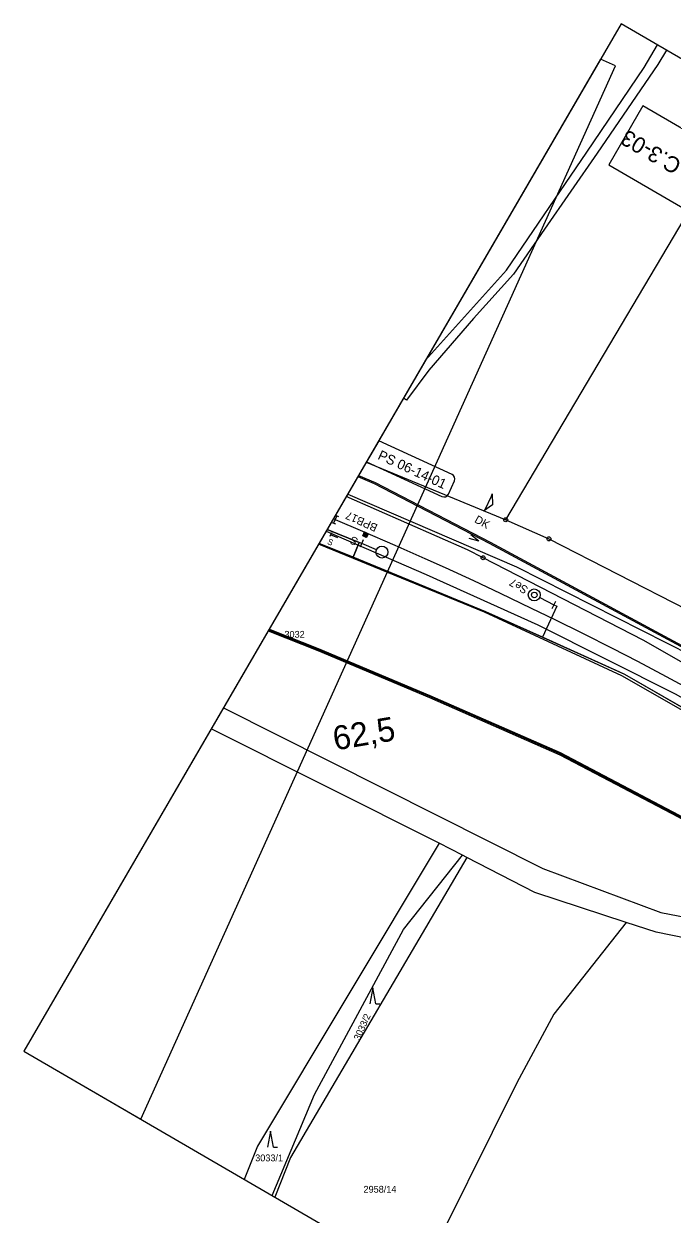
# Model space of a CAD drawing. Extents: x -621168 to -620292, y -1122748 to -1122069.
# Drawn here: x -621167.8 to -621005.8, y -1122366.6 to -1122069.2 of the extents above; entities that cross this region are included whole.
import ezdxf

# ---------------------------------------------------------------- set-up
doc = ezdxf.new("R2010")
doc.units = 0
for name, color, linetype in [('CETIN', 7, 'Continuous'), ('hm', 7, 'Continuous'), ('HranDP', 7, 'Continuous'), ('Hranice parcel', 7, 'Continuous'), ('itself', 7, 'Continuous'), ('lomové body trasa', 7, 'Continuous'), ('Parcelní čísla', 7, 'Continuous'), ('PS 06-14-01_trasa_sdělovací_nové', 7, 'Continuous'), ('PS6-14-01_bubliny', 7, 'Continuous'), ('Razítka', 7, 'Continuous'), ('Rámečky-tisk', 7, 'Continuous'), ('SSZT', 7, 'Continuous'), ('SSZT-DK', 7, 'Continuous'), ('STANICENI NOVE HM', 7, 'Continuous'), ('Vrstva 1', 7, 'Continuous'), ('Vrstva 2', 7, 'Continuous'), ('Vrstva 3', 7, 'Continuous'), ('Vrstva 6', 7, 'Continuous'), ('Věcná břemena k části', 7, 'Continuous'), ('Značky bodu BP', 7, 'Continuous'), ('Značky kultur', 7, 'Continuous'), ('ČD-T', 7, 'Continuous')]:
    doc.layers.add(name, color=color, linetype=linetype)

msp = doc.modelspace()

# ---------------------------------------------------------------- linework, layer by layer
at = {"layer": 'CETIN'}
msp.add_lwpolyline([(-621086.89, -1122186.72), (-621044.7, -1122204.84), (-620975.94, -1122239.69), (-620943.1, -1122258.62), (-620748.44, -1122376.27), (-620484.52, -1122538.15)], dxfattribs=at)
at = {"layer": 'hm'}
msp.add_line((-621052.05, -1122209.91), (-621052.05, -1122209.91), dxfattribs=at)
at = {"layer": 'HranDP'}
for points in [[(-620988.93, -1122236.95), (-621013.01, -1122223.23), (-621053.04, -1122202.61), (-621056.92, -1122200.6), (-621087.23, -1122187.32)], [(-620902.62, -1122306.44), (-620922.25, -1122290.14), (-620980.18, -1122253.91), (-621018.36, -1122232.1), (-621052.69, -1122216.23), (-621094.17, -1122199.24)]]:
    msp.add_lwpolyline(points, dxfattribs=at)
at = {"layer": 'Hranice parcel'}
for p, q in [((-621058.23, -1122276.92), (-621064.04, -1122273.91)), ((-621057.09, -1122277.51), (-621058.23, -1122276.92))]:
    msp.add_line(p, q, dxfattribs=at)
for points in [[(-621007.22, -1122075.75), (-621009.34, -1122079.37), (-621024.57, -1122101.49), (-621037.72, -1122120.47), (-621045.46, -1122131.72), (-621055.41, -1122142.78), (-621066.65, -1122155.68), (-621072.18, -1122163.23), (-621072.95, -1122162.75)], [(-621067.43, -1122153.26), (-621047.24, -1122130.75), (-621027.16, -1122101.24), (-621012.76, -1122080.08), (-621009.44, -1122074.46)], [(-621047.4, -1122193.11), (-620985.28, -1122088.51)], [(-621082.25, -1122178.75), (-621047.4, -1122193.11)], [(-620988.93, -1122236.95), (-621013.01, -1122223.23), (-621053.04, -1122202.61), (-621056.92, -1122200.6), (-621087.23, -1122187.32)], [(-621047.4, -1122193.11), (-621036.61, -1122197.87), (-621002.15, -1122215.49)], [(-620902.62, -1122306.44), (-620922.25, -1122290.14), (-620980.18, -1122253.91), (-621018.36, -1122232.1), (-621052.69, -1122216.23), (-621094.17, -1122199.24)], [(-621117.92, -1122240.09), (-621038.08, -1122280.28), (-621008.67, -1122291.25), (-620981.77, -1122296.39), (-620925.27, -1122300.21), (-620902.62, -1122306.44)], [(-621064.04, -1122273.91), (-621121, -1122245.38)], [(-621064.04, -1122273.91), (-621109.46, -1122349.65), (-621112.72, -1122357.96)], [(-621105.8, -1122361.99), (-621095.18, -1122336.72), (-621072.95, -1122295.49), (-621058.23, -1122276.92)], [(-621057.09, -1122277.51), (-621101.17, -1122352.49), (-621105.1, -1122362.4)], [(-621017.3, -1122293.74), (-621040.1, -1122286.26), (-621057.09, -1122277.51)], [(-621017.3, -1122293.74), (-621035.39, -1122316.61), (-621044.64, -1122333.8), (-621069.23, -1122383.25)], [(-620940.78, -1122305.04), (-620976.17, -1122302.17), (-620982.88, -1122301.63), (-621009.79, -1122296.2), (-621017.3, -1122293.74)]]:
    msp.add_lwpolyline(points, dxfattribs=at)
at = {"layer": 'itself'}
msp.add_lwpolyline([(-620939.77, -1122306.09), (-620941.93, -1122303.88), (-620947.14, -1122298.36), (-620948.95, -1122297.23), (-620977.47, -1122282.26), (-621004.21, -1122267.13), (-621033.79, -1122251.59), (-621066.38, -1122237.31), (-621094.27, -1122225.57), (-621106.27, -1122220.82), (-621106.63, -1122220.67)], dxfattribs=at)
at = {"layer": 'lomové body trasa'}
msp.add_line((-621092.03, -1122195.56), (-621084.03, -1122198.76), dxfattribs=at)
at = {"layer": 'PS 06-14-01_trasa_sdělovací_nové'}
msp.add_lwpolyline([(-620756.33, -1122383.52), (-620759.75, -1122381.36), (-620756.35, -1122375.21), (-620764.72, -1122371.2), (-620767.85, -1122376.3), (-620853.07, -1122323.34), (-620895.69, -1122296.63), (-620912.11, -1122286.23), (-620914.88, -1122290.62), (-620964.54, -1122259.53), (-620982.11, -1122249.22), (-620983.24, -1122251.5), (-621017.63, -1122231.73), (-621052.34, -1122216.08), (-621085.52, -1122202.49), (-621084.03, -1122198.76), (-621092.03, -1122195.56)], dxfattribs=at)
at = {"layer": 'PS6-14-01_bubliny'}
for p, q in [((-621079.11, -1122173.35), (-621082.19, -1122178.64)), ((-621060.81, -1122181.76), (-621079.11, -1122173.35)), ((-621082.19, -1122178.64), (-621063.35, -1122187.3)), ((-621061.73, -1122186.7), (-621060.21, -1122183.38))]:
    msp.add_line(p, q, dxfattribs=at)
for points in [[(-621050.82, -1122186.62), (-621050.66, -1122189.41), (-621052.97, -1122190.98)], [(-621052.56, -1122190.51), (-621050.94, -1122187.23)]]:
    msp.add_lwpolyline(points, dxfattribs=at)
for centre, start, end in [((-621061.31, -1122182.87), 335.3299, 65.3299), ((-621062.84, -1122186.19), 245.3299, 335.3299), ((-621052.04, -1122186.69), 333.67, 3.222), ((-621053.66, -1122189.97), 304.1183, 333.67)]:
    msp.add_arc(centre, 1.22, start, end, dxfattribs=at)
at = {"layer": 'Razítka'}
msp.add_lwpolyline([(-620935.31, -1122134.91), (-621013.11, -1122089.68), (-621021.65, -1122104.37), (-620943.86, -1122149.61)], close=True, dxfattribs=at)
at = {"layer": 'Rámečky-tisk'}
for points in [[(-621018.54, -1122069.17), (-621167.83, -1122325.92), (-620441.66, -1122748.16)], [(-620441.66, -1122748.16), (-620292.37, -1122491.41), (-621018.54, -1122069.17)], [(-621023.68, -1122078.01), (-621167.83, -1122325.92), (-621138.62, -1122342.9)], [(-621138.62, -1122342.9), (-621019.96, -1122079.69), (-621023.68, -1122078.01)]]:
    msp.add_lwpolyline(points, dxfattribs=at)
at = {"layer": 'SSZT'}
for q in [(-621056.08, -1122196.86), (-621056.56, -1122197.82)]:
    msp.add_line((-621054.08, -1122198.46), q, dxfattribs=at)
msp.add_lwpolyline([(-621092.26, -1122195.95), (-621067.31, -1122206.75), (-621039.37, -1122219.34), (-621005.03, -1122236.61), (-620978.62, -1122251.49), (-620945.97, -1122271.24), (-620879.24, -1122313.32)], dxfattribs=at)
at = {"layer": 'SSZT-DK'}
msp.add_lwpolyline([(-621084.33, -1122182.33), (-621080.25, -1122184.04), (-621051.5, -1122198.93), (-620999.37, -1122227), (-620959.93, -1122250.54), (-620931.35, -1122267.52), (-620900.27, -1122286.47), (-620889.15, -1122293.45), (-620783.74, -1122358.82), (-620712.75, -1122398.18), (-620653.12, -1122435.23), (-620617.36, -1122456.74), (-620574.42, -1122482.6), (-620528.16, -1122511.11), (-620496.31, -1122530.83), (-620515.02, -1122558.81), (-620500.38, -1122568.61), (-620465.39, -1122591.45), (-620452.16, -1122605.02), (-620438.23, -1122615.5), (-620392.31, -1122655.21), (-620389.25, -1122658.02)], dxfattribs=at)
at = {"layer": 'Vrstva 1'}
for p, q in [((-621034.66, -1122214.7), (-621037.18, -1122220.24)), ((-621035.34, -1122214.37), (-621034.66, -1122214.7)), ((-621037.18, -1122220.24), (-621038.19, -1122222.46))]:
    msp.add_line(p, q, dxfattribs=at)
for points in [[(-621090.46, -1122192.86), (-621090.02, -1122193.05), (-621083.15, -1122195.96), (-621075.1, -1122199.44), (-621067.62, -1122202.75), (-621062.51, -1122205.06), (-621055.44, -1122208.32), (-621048.79, -1122211.44), (-621041, -1122215.18), (-621035.25, -1122217.98), (-621028.06, -1122221.55), (-621020.8, -1122225.22), (-621014.49, -1122228.46), (-621007.27, -1122232.26), (-620999.51, -1122236.43)], [(-621085.52, -1122202.49), (-621094.03, -1122199)], [(-621083.39, -1122199.04), (-621084.03, -1122198.76), (-621085.52, -1122202.49)], [(-621038.19, -1122222.46), (-621052.34, -1122216.08), (-621080.17, -1122204.68), (-621085.52, -1122202.49)], [(-620932.81, -1122279.39), (-620953.35, -1122266.52), (-620964.54, -1122259.53), (-620979.4, -1122250.79), (-620982.11, -1122249.22), (-620983.24, -1122251.5), (-620999.51, -1122242.21), (-621017.63, -1122231.73), (-621018.87, -1122231.17), (-621038.19, -1122222.46)]]:
    msp.add_lwpolyline(points, dxfattribs=at)
at = {"layer": 'Vrstva 2'}
for p, q in [((-621083.12, -1122197.06), (-621081.8, -1122196.57)), ((-621083.04, -1122196.89), (-621081.97, -1122196.5)), ((-621083.03, -1122197.16), (-621081.8, -1122196.71)), ((-621082.96, -1122196.72), (-621082.14, -1122196.42)), ((-621082.88, -1122196.55), (-621082.31, -1122196.34)), ((-621082.86, -1122197.24), (-621081.88, -1122196.88)), ((-621082.8, -1122196.38), (-621082.48, -1122196.26)), ((-621082.73, -1122196.21), (-621082.65, -1122196.19)), ((-621082.69, -1122197.32), (-621081.96, -1122197.05)), ((-621082.52, -1122197.4), (-621082.03, -1122197.22)), ((-621082.36, -1122197.48), (-621082.11, -1122197.39)), ((-621083, -1122198.12), (-621083.78, -1122199.96)), ((-621079.7, -1122200.6), (-621083.39, -1122199.04)), ((-621038.91, -1122212.56), (-621035.34, -1122214.37)), ((-621035.79, -1122215.26), (-621034.89, -1122213.48))]:
    msp.add_line(p, q, dxfattribs=at)
msp.add_lwpolyline([(-621082.7, -1122196.16), (-621081.75, -1122196.6), (-621082.19, -1122197.55), (-621083.14, -1122197.11)], close=True, dxfattribs=at)
msp.add_lwpolyline([(-621082.7, -1122196.16), (-621081.75, -1122196.6), (-621082.19, -1122197.55), (-621083.14, -1122197.11)], close=True, dxfattribs=at)
for centre, radius in [((-621078.32, -1122201.18), 1.5), ((-621040.25, -1122211.89), 1.5), ((-621040.25, -1122211.89), 0.7)]:
    msp.add_circle(centre, radius, dxfattribs=at)
at = {"layer": 'Vrstva 3'}
for p, q in [((-621090.87, -1122193.78), (-621089.95, -1122194.16)), ((-621089.64, -1122192.13), (-621090.41, -1122193.97)), ((-621089.95, -1122191.99), (-621089.18, -1122192.32))]:
    msp.add_line(p, q, dxfattribs=at)
at = {"layer": 'Vrstva 6'}
for p, q in [((-621090.97, -1122196.38), (-621091.37, -1122197.3)), ((-621089.36, -1122197.63), (-621091.17, -1122196.84))]:
    msp.add_line(p, q, dxfattribs=at)
at = {"layer": 'Věcná břemena k části'}
msp.add_line((-621106.51, -1122220.46), (-621106.76, -1122220.89), dxfattribs=at)
msp.add_lwpolyline([(-621106.76, -1122220.89), (-621106.36, -1122221.05), (-621094.36, -1122225.8), (-621066.48, -1122237.54), (-621033.9, -1122251.82), (-621004.33, -1122267.35), (-620977.59, -1122282.48), (-620949.07, -1122297.45), (-620947.3, -1122298.56), (-620947.13, -1122298.73), (-620946.39, -1122298.78), (-620946.98, -1122298.16), (-620948.83, -1122297.01), (-620977.35, -1122282.04), (-621004.09, -1122266.91), (-621033.68, -1122251.36), (-621066.28, -1122237.08), (-621094.18, -1122225.34), (-621106.18, -1122220.59), (-621106.51, -1122220.46)], dxfattribs=at)
at = {"layer": 'Značky bodu BP'}
for centre, radius in [((-621047.4, -1122193.11), 0.5), ((-621047.4, -1122193.11), 0.0303), ((-621036.61, -1122197.87), 0.5), ((-621036.61, -1122197.87), 0.0303), ((-621053.04, -1122202.61), 0.5), ((-621053.04, -1122202.61), 0.0303)]:
    msp.add_circle(centre, radius, dxfattribs=at)
at = {"layer": 'Značky kultur'}
for p, q in [((-621080.58, -1122310.04), (-621081.33, -1122314.04)), ((-621079.83, -1122314.04), (-621080.58, -1122310.04)), ((-621079.83, -1122314.04), (-621078.83, -1122314.04)), ((-621106.14, -1122345.91), (-621106.89, -1122349.91)), ((-621105.39, -1122349.91), (-621106.14, -1122345.91)), ((-621105.39, -1122349.91), (-621104.39, -1122349.91))]:
    msp.add_line(p, q, dxfattribs=at)
at = {"layer": 'ČD-T'}
msp.add_lwpolyline([(-621084.19, -1122182.07), (-621080.06, -1122183.8), (-621051.32, -1122198.69), (-620999.18, -1122226.77), (-620959.75, -1122250.31), (-620931.16, -1122267.28), (-620900.08, -1122286.23), (-620888.96, -1122293.22), (-620783.56, -1122358.58), (-620712.56, -1122397.94), (-620652.93, -1122435), (-620617.18, -1122456.5), (-620574.24, -1122482.37), (-620527.97, -1122510.87), (-620481.08, -1122540.08), (-620497, -1122565.38), (-620499.27, -1122568.98), (-620465.21, -1122591.22), (-620451.97, -1122604.79), (-620438.05, -1122615.26), (-620392.12, -1122654.98), (-620389.1, -1122657.76)], dxfattribs=at)

# ---------------------------------------------------------------- texts
at = {"layer": 'Parcelní čísla'}
for s, p in [('3032', (-621102.69, -1122222.58)), ('3033/1', (-621110, -1122353.42)), ('2958/14', (-621082.93, -1122361.26))]:
    msp.add_text(s, height=1.7, dxfattribs=at).set_placement(p)
msp.add_text('3033/2', height=1.7, rotation=66, dxfattribs=at).set_placement((-621083.91, -1122323.36))
at = {"layer": 'PS6-14-01_bubliny'}
msp.add_text('PS 06-14-01', height=2.4384, rotation=335.3299, dxfattribs=at).set_placement((-621079.56, -1122177.84))
at = {"layer": 'Razítka'}
msp.add_text('C.3-03', height=4, rotation=149.8236, dxfattribs=at).set_placement((-621003.15, -1122103.55))
at = {"layer": 'SSZT-DK'}
msp.add_text('DK', height=2, rotation=330.9216, dxfattribs=at).set_placement((-621055.37, -1122193.63))
at = {"layer": 'STANICENI NOVE HM'}
msp.add_text('62,5', height=6, rotation=9.6991, dxfattribs=at).set_placement((-621090.05, -1122250.78))
at = {"layer": 'Vrstva 3'}
for s, rotation, p in [('BPB17', 155.7341, (-621079.23, -1122194.37)), ('S', 155.7341, (-621084.1, -1122197.86)), ('Se7', 149.8236, (-621041.61, -1122210.04))]:
    msp.add_text(s, height=2, rotation=rotation, dxfattribs=at).set_placement(p)
at = {"layer": 'Vrstva 6'}
msp.add_text('S', height=1.5, rotation=336.4373, dxfattribs=at).set_placement((-621092.12, -1122199.11))

doc.saveas('drawing.dxf')
